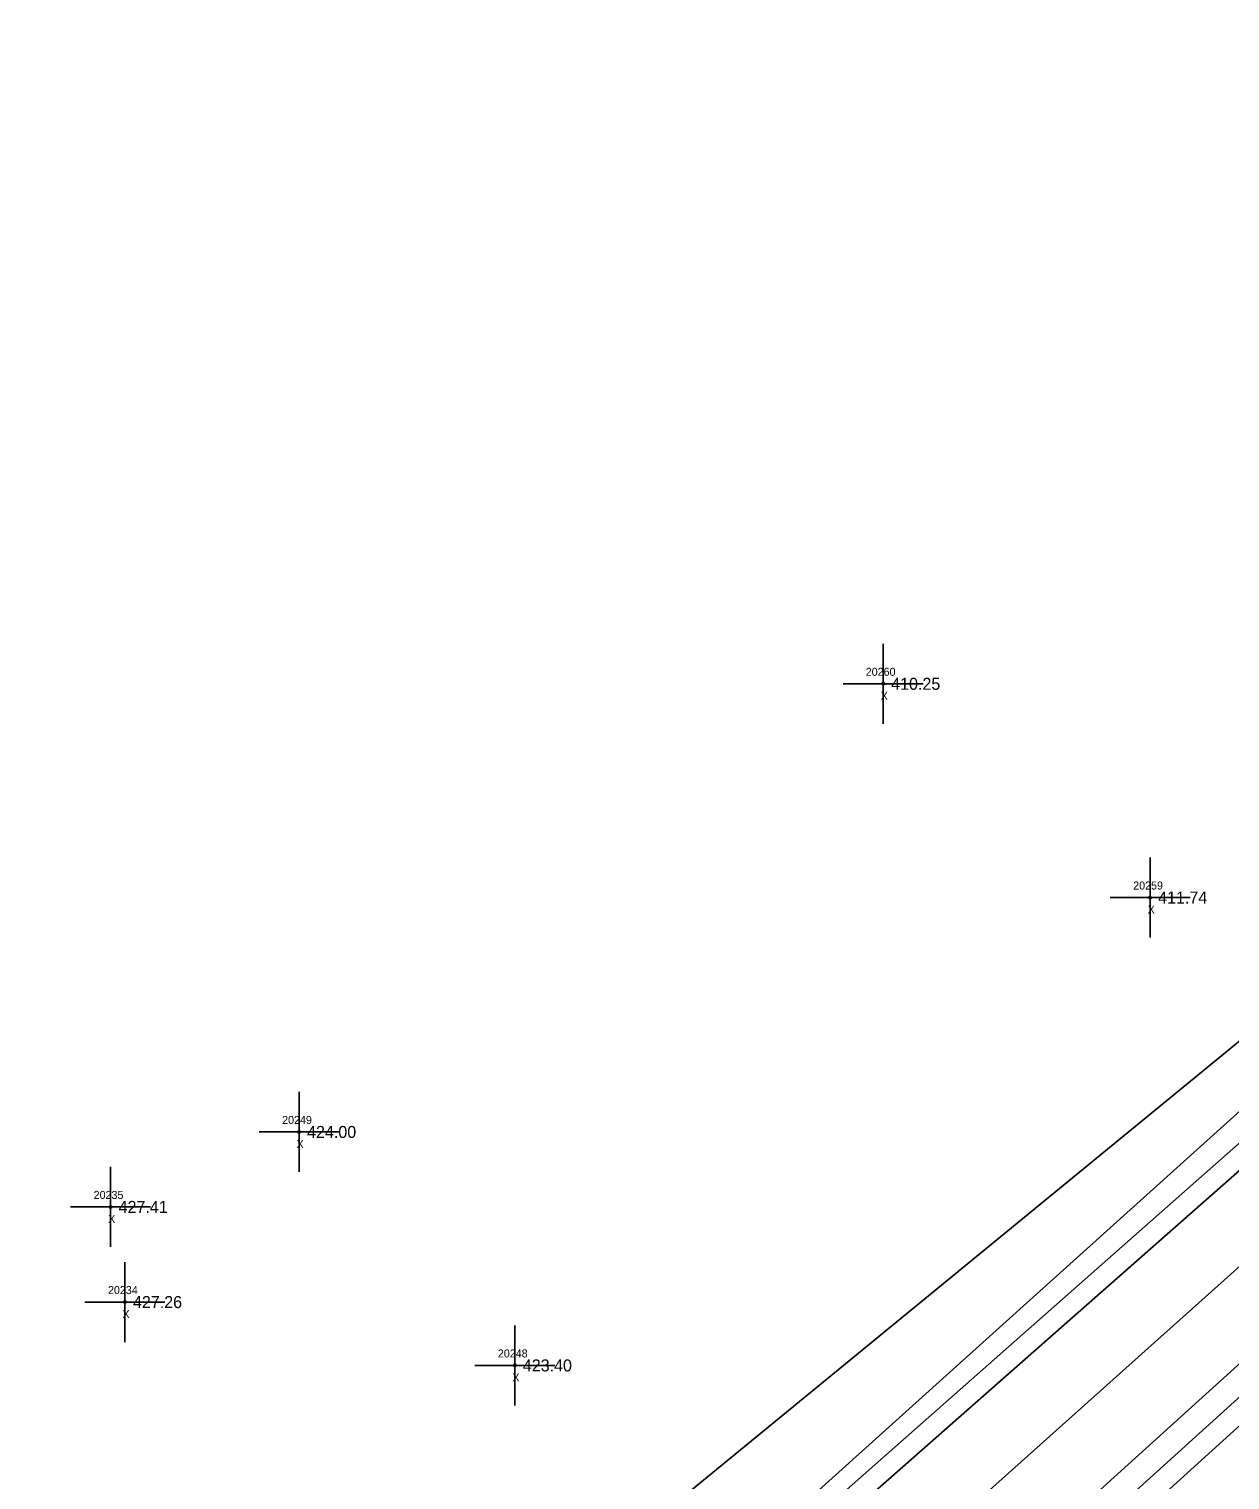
# Model space of a CAD drawing. Extents: x 2116373 to 2118139, y 979529 to 981026.
# Drawn here: x 2117006.3 to 2117156.4, y 979946 to 980127.3 of the extents above; entities that cross this region are included whole.
import ezdxf

# ---------------------------------------------------------------- set-up
doc = ezdxf.new("R2010")
doc.units = 0
for name, color, linetype in [('RD_DTM_BkLn1', 7, 'Continuous'), ('RD_DTM_BkLn2', 7, 'Continuous'), ('RD_EX_H2O', 7, 'Continuous'), ('RD_EX_Misc', 7, 'Continuous'), ('RD_EX_Misc_txCode', 7, 'Continuous'), ('RD_EX_Road', 7, 'Continuous'), ('RD_EX_TX_Misc_ELEV', 7, 'Continuous'), ('RD_SMD_Locator', 7, 'Continuous')]:
    doc.layers.add(name, color=color, linetype=linetype)

msp = doc.modelspace()

# ---------------------------------------------------------------- linework, layer by layer
at = {"layer": 'RD_DTM_BkLn1'}
msp.add_lwpolyline([(2116414.21, 979630.19), (2116468.62, 979643.23), (2116521.45, 979653.6), (2116618.87, 979670.38), (2116668.4, 979680.7), (2116717.3, 979694.48), (2116764.56, 979711.13), (2116810.15, 979729.38), (2116856.49, 979749.81), (2116900.74, 979773.15), (2116944.03, 979798.93), (2116982.75, 979824.6), (2117026.56, 979857.02), (2117064.34, 979888.81), (2117101.78, 979922.69), (2117176.3, 979989.4), (2117250.99, 980056.19), (2117326.56, 980126.36)], dxfattribs=at)
at = {"layer": 'RD_DTM_BkLn2'}
for points in [[(2116410.78, 979641.79), (2116465.45, 979654.97), (2116518.83, 979664.89), (2116614.96, 979683.75), (2116663.75, 979692.58), (2116713.02, 979705.22), (2116760.07, 979721.97), (2116804.88, 979741.47), (2116850.79, 979761.38), (2116894.83, 979783.88), (2116937.98, 979807.44), (2116977.39, 979833.6), (2117020.56, 979865.29), (2117056.86, 979896.38), (2117094.29, 979932.2), (2117168.14, 979997.38), (2117238.71, 980069.61), (2117312.33, 980134.21), (2117318.43, 980135.16)], [(2116408.48, 979653.74), (2116461.38, 979665.42), (2116520.7, 979678.48), (2116616.28, 979695.74), (2116661.37, 979703.79), (2116711.18, 979715.21), (2116757.77, 979732.03), (2116802.04, 979749.54), (2116847.76, 979769.63), (2116889.13, 979795.82), (2116931.32, 979820.72), (2116972.01, 979847.71), (2117009.67, 979877.33), (2117051.05, 979910.18), (2117086.71, 979942.74), (2117161.4, 980003.96), (2117222.13, 980080.24), (2117265.44, 980120.03)], [(2116417.57, 979618.2), (2116471.29, 979630.11), (2116523.91, 979640.31), (2116563.87, 979646.21), (2116622.92, 979650.9), (2116673.37, 979660.68), (2116721.38, 979672.44), (2116775.31, 979687.3), (2116820.23, 979708.52), (2116865.35, 979734.51), (2116907.21, 979760.29), (2116934.42, 979772.82), (2116951.5, 979788.78), (2116990.39, 979814.35), (2117033.97, 979847.22), (2117071.26, 979879.46), (2117111.32, 979914.45), (2117184.14, 979980.37), (2117264.18, 980040.84), (2117335.34, 980108.05), (2117336.43, 980115.6)]]:
    msp.add_lwpolyline(points, dxfattribs=at)
at = {"layer": 'RD_EX_H2O'}
for points in [[(2116411.09, 979644.42), (2116463.93, 979657.73), (2116517.88, 979668.38), (2116615.09, 979686.35), (2116663.35, 979695.16), (2116711.62, 979708.91), (2116758.49, 979726.13), (2116778.25, 979736.27), (2116803.5, 979744.47), (2116849.89, 979764.23), (2116894.14, 979786.32), (2116936.31, 979809.39), (2116976.21, 979834.9), (2117018.41, 979867.86), (2117054.24, 979898.91), (2117093.35, 979934.14), (2117166.11, 979999.69), (2117224.07, 980077.92), (2117265.44, 980120.03)], [(2116934.42, 979772.82), (2116952.72, 979786.01), (2116992.31, 979812.05), (2117036.21, 979845.2), (2117073.01, 979877), (2117113.79, 979913.05), (2117185.72, 979978.24), (2117270.2, 980032.33), (2117344.8, 980095.54)]]:
    msp.add_lwpolyline(points, dxfattribs=at)
at = {"layer": 'RD_EX_Misc'}
for p, q in [((2117113.08, 980040.48), (2117113.08, 980050.48)), ((2117108.08, 980045.48), (2117118.08, 980045.48)), ((2117146.44, 980013.77), (2117146.44, 980023.77)), ((2117141.44, 980018.77), (2117151.44, 980018.77)), ((2117040.09, 979984.47), (2117040.09, 979994.47)), ((2117035.09, 979989.47), (2117045.09, 979989.47)), ((2117016.54, 979975.1), (2117016.54, 979985.1)), ((2117011.54, 979980.1), (2117021.54, 979980.1)), ((2117018.33, 979963.21), (2117018.33, 979973.21)), ((2117013.33, 979968.21), (2117023.33, 979968.21)), ((2117067.05, 979955.29), (2117067.05, 979965.29)), ((2117062.05, 979960.29), (2117072.05, 979960.29))]:
    msp.add_line(p, q, dxfattribs=at)
at = {"layer": 'RD_EX_Road'}
for points in [[(2116412.2, 979638.84), (2116468.17, 979651.36), (2116519.2, 979662.5), (2116617.24, 979678.85), (2116665.51, 979689.1), (2116714.23, 979702.46), (2116761.42, 979719.35), (2116806.99, 979737.42), (2116852.23, 979758.11), (2116896.57, 979780.91), (2116939.1, 979805.52), (2116978.46, 979832.1), (2117021.29, 979863.87), (2117058.15, 979895.61), (2117096.06, 979930.47), (2117170.14, 979995.71), (2117244.91, 980062.82), (2117320.63, 980133.49), (2117326.56, 980126.36)], [(2116416.36, 979621.21), (2116470.51, 979634.11), (2116523.97, 979644.68), (2116620.55, 979661.21), (2116670.7, 979671.96), (2116720.65, 979685.84), (2116767.66, 979702.22), (2116814.07, 979721.02), (2116860.35, 979742.3), (2116904.9, 979765.18), (2116949.06, 979791.19), (2116988.09, 979817.15), (2117031.94, 979849.78), (2117069.79, 979881.53), (2117108.89, 979916.38), (2117182.06, 979982.67), (2117257.56, 980049.29), (2117334.73, 980117.38), (2117326.56, 980126.36)]]:
    msp.add_lwpolyline(points, dxfattribs=at)
at = {"layer": 'RD_SMD_Locator'}
for centre in [(2117113.08, 980045.48), (2117146.44, 980018.77), (2117040.09, 979989.47), (2117016.54, 979980.1), (2117018.33, 979968.21), (2117067.05, 979960.29)]:
    msp.add_circle(centre, 0.15, dxfattribs=at)

# ---------------------------------------------------------------- texts
at = {"layer": 'RD_EX_Misc_txCode'}
for s, p in [('20260', (2117110.9, 980046.48)), ('X', (2117112.77, 980043.48)), ('20259', (2117144.32, 980019.77)), ('X', (2117146.13, 980016.77)), ('20249', (2117037.97, 979990.47)), ('X', (2117039.77, 979987.47)), ('20235', (2117014.42, 979981.1)), ('X', (2117016.23, 979978.1)), ('20234', (2117016.21, 979969.21)), ('X', (2117018.02, 979966.21)), ('20248', (2117064.93, 979961.29)), ('X', (2117066.74, 979958.29))]:
    msp.add_text(s, height=1, dxfattribs=at).set_placement(p)
at = {"layer": 'RD_EX_TX_Misc_ELEV'}
for s, p in [('410.25', (2117114.08, 980044.73)), ('411.74', (2117147.44, 980018.02)), ('424.00', (2117041.09, 979988.72)), ('427.41', (2117017.54, 979979.35)), ('427.26', (2117019.33, 979967.46)), ('423.40', (2117068.05, 979959.54))]:
    msp.add_text(s, height=1.5, dxfattribs=at).set_placement(p)

doc.saveas('drawing.dxf')
